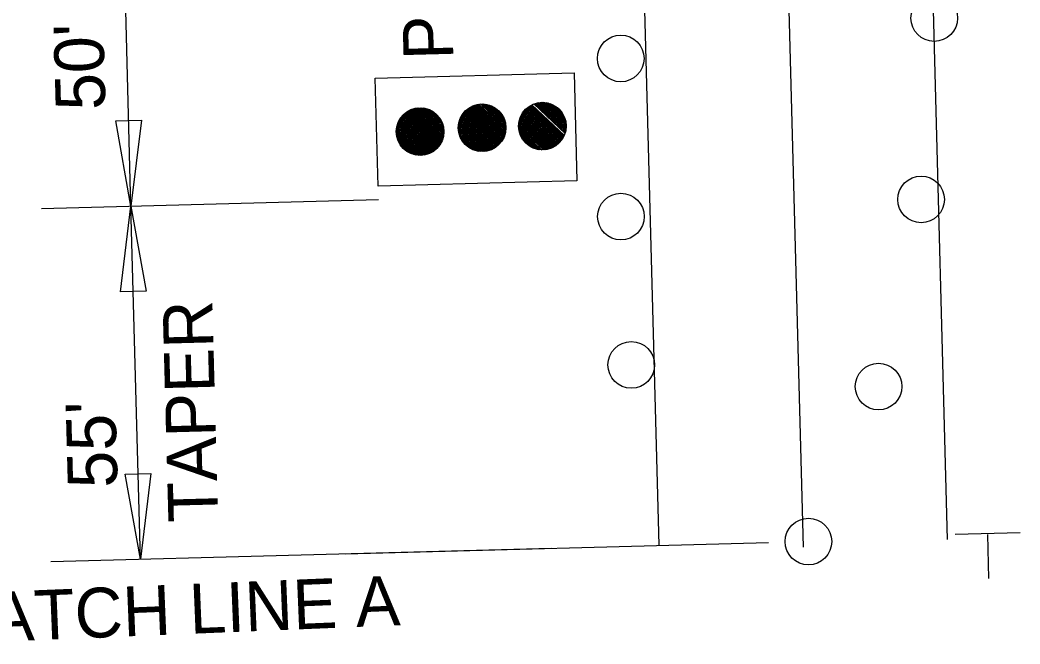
# Model space of a CAD drawing. Extents: x 1929624 to 1932072, y 596315 to 605533.
# Drawn here: x 1931264.8 to 1931385.3, y 596662 to 596737.2 of the extents above; entities that cross this region are included whole.
import ezdxf

# ---------------------------------------------------------------- set-up
doc = ezdxf.new("R2010")
doc.units = 0
doc.layers.add('Default', color=7, linetype='Continuous')

msp = doc.modelspace()

# ---------------------------------------------------------------- linework, layer by layer
at = {"layer": 'Default'}
for p, q in [((1931376.6, 596674.64), (1931372.56, 596825.19)), ((1931359.23, 596673.68), (1931355.29, 596820.56)), ((1931341.84, 596673.92), (1931337.95, 596818.64)), ((1931278.16, 596714.79), (1931277.26, 596748.45)), ((1931315.51, 596722.34), (1931311.46, 596726.18)), ((1931315.57, 596722.45), (1931311.57, 596726.25)), ((1931315.63, 596722.57), (1931311.68, 596726.31)), ((1931315.68, 596722.69), (1931311.8, 596726.37)), ((1931315.73, 596722.82), (1931311.93, 596726.42)), ((1931315.77, 596722.95), (1931312.06, 596726.47)), ((1931315.81, 596723.09), (1931312.19, 596726.52)), ((1931315.84, 596723.23), (1931312.34, 596726.55)), ((1931315.86, 596723.38), (1931312.48, 596726.59)), ((1931315.88, 596723.54), (1931312.64, 596726.61)), ((1931315.89, 596723.71), (1931312.8, 596726.63)), ((1931315.88, 596723.88), (1931312.98, 596726.63)), ((1931315.87, 596724.07), (1931313.16, 596726.63)), ((1931315.84, 596724.26), (1931313.36, 596726.61)), ((1931315.79, 596724.48), (1931313.58, 596726.58)), ((1931315.72, 596724.72), (1931313.83, 596726.52)), ((1931315.6, 596725.01), (1931314.12, 596726.41)), ((1931315.38, 596725.39), (1931314.52, 596726.21)), ((1931322.62, 596722.29), (1931318.44, 596726.25)), ((1931322.7, 596722.39), (1931318.53, 596726.33)), ((1931322.78, 596722.49), (1931318.63, 596726.42)), ((1931322.85, 596722.59), (1931318.73, 596726.5)), ((1931322.92, 596722.69), (1931318.83, 596726.57)), ((1931322.99, 596722.8), (1931318.93, 596726.64)), ((1931323.05, 596722.92), (1931319.04, 596726.71)), ((1931323.1, 596723.04), (1931319.16, 596726.77)), ((1931323.16, 596723.16), (1931319.28, 596726.83)), ((1931323.2, 596723.29), (1931319.4, 596726.89)), ((1931323.25, 596723.42), (1931319.53, 596726.94)), ((1931323.28, 596723.56), (1931319.67, 596726.98)), ((1931323.31, 596723.7), (1931319.81, 596727.02)), ((1931323.34, 596723.85), (1931319.96, 596727.05)), ((1931323.35, 596724.01), (1931320.11, 596727.07)), ((1931323.36, 596724.17), (1931320.28, 596727.09)), ((1931323.36, 596724.34), (1931320.45, 596727.1)), ((1931323.35, 596724.53), (1931320.64, 596727.09)), ((1931323.32, 596724.73), (1931320.84, 596727.08)), ((1931323.27, 596724.95), (1931321.06, 596727.04)), ((1931323.19, 596725.19), (1931321.3, 596726.98)), ((1931323.08, 596725.47), (1931321.6, 596726.88)), ((1931322.85, 596725.86), (1931321.99, 596726.67)), ((1931329.66, 596722.26), (1931325.5, 596726.2)), ((1931329.75, 596722.35), (1931325.58, 596726.3)), ((1931329.84, 596722.44), (1931325.66, 596726.39)), ((1931329.92, 596722.53), (1931325.75, 596726.48)), ((1931330, 596722.63), (1931325.84, 596726.57)), ((1931330.08, 596722.73), (1931325.94, 596726.65)), ((1931330.15, 596722.83), (1931326.04, 596726.73)), ((1931330.22, 596722.94), (1931326.14, 596726.8)), ((1931330.28, 596723.05), (1931326.25, 596726.87)), ((1931330.34, 596723.16), (1931326.36, 596726.93)), ((1931330.4, 596723.28), (1931326.48, 596727)), ((1931330.49, 596723.54), (1931326.73, 596727.1)), ((1931330.53, 596723.67), (1931326.86, 596727.15)), ((1931330.56, 596723.81), (1931327, 596727.19)), ((1931330.59, 596723.96), (1931327.14, 596727.23)), ((1931330.61, 596724.11), (1931327.29, 596727.26)), ((1931330.63, 596724.27), (1931327.45, 596727.28)), ((1931330.63, 596724.44), (1931327.62, 596727.29)), ((1931330.62, 596724.62), (1931327.8, 596727.29)), ((1931330.6, 596724.81), (1931327.99, 596727.28)), ((1931330.57, 596725.02), (1931328.2, 596727.26)), ((1931330.51, 596725.24), (1931328.43, 596727.21)), ((1931330.42, 596725.5), (1931328.69, 596727.14)), ((1931330.26, 596725.82), (1931329.02, 596727)), ((1931329.87, 596726.37), (1931329.59, 596726.63)), ((1931276.34, 596725.05), (1931279.43, 596725.14)), ((1931278.16, 596714.79), (1931276.34, 596725.05)), ((1931279.43, 596725.14), (1931278.16, 596714.79)), ((1931314.45, 596721.27), (1931310.45, 596725.07)), ((1931314.57, 596721.34), (1931310.51, 596725.18)), ((1931314.67, 596721.41), (1931310.58, 596725.29)), ((1931314.77, 596721.49), (1931310.65, 596725.4)), ((1931314.87, 596721.57), (1931310.72, 596725.5)), ((1931314.96, 596721.65), (1931310.8, 596725.6)), ((1931315.05, 596721.74), (1931310.88, 596725.69)), ((1931315.14, 596721.83), (1931310.97, 596725.78)), ((1931315.22, 596721.92), (1931311.06, 596725.87)), ((1931315.3, 596722.02), (1931311.15, 596725.95)), ((1931315.37, 596722.12), (1931311.25, 596726.03)), ((1931315.44, 596722.23), (1931311.35, 596726.11)), ((1931321.44, 596721.51), (1931317.73, 596725.03)), ((1931321.57, 596721.56), (1931317.77, 596725.16)), ((1931321.7, 596721.62), (1931317.82, 596725.29)), ((1931321.81, 596721.67), (1931317.87, 596725.41)), ((1931321.93, 596721.74), (1931317.93, 596725.53)), ((1931322.04, 596721.81), (1931317.99, 596725.65)), ((1931322.15, 596721.88), (1931318.05, 596725.76)), ((1931322.25, 596721.95), (1931318.12, 596725.86)), ((1931322.35, 596722.03), (1931318.2, 596725.96)), ((1931322.44, 596722.11), (1931318.28, 596726.06)), ((1931322.53, 596722.2), (1931318.36, 596726.16)), ((1931328.49, 596721.64), (1931324.94, 596725.01)), ((1931328.63, 596721.68), (1931324.97, 596725.15)), ((1931328.77, 596721.73), (1931325.01, 596725.29)), ((1931328.89, 596721.78), (1931325.06, 596725.42)), ((1931329.02, 596721.84), (1931325.11, 596725.54)), ((1931329.13, 596721.9), (1931325.16, 596725.66)), ((1931329.25, 596721.96), (1931325.22, 596725.78)), ((1931329.36, 596722.03), (1931325.28, 596725.89)), ((1931329.46, 596722.1), (1931325.35, 596726)), ((1931329.56, 596722.18), (1931325.42, 596726.1)), ((1931313.38, 596720.91), (1931310.14, 596723.98)), ((1931313.22, 596720.89), (1931310.14, 596723.82)), ((1931313.54, 596720.93), (1931310.16, 596724.14)), ((1931313.69, 596720.97), (1931310.19, 596724.29)), ((1931313.83, 596721), (1931310.22, 596724.43)), ((1931313.97, 596721.05), (1931310.25, 596724.57)), ((1931314.1, 596721.1), (1931310.29, 596724.7)), ((1931314.22, 596721.15), (1931310.34, 596724.83)), ((1931314.34, 596721.21), (1931310.39, 596724.95)), ((1931320.7, 596721.36), (1931317.61, 596724.28)), ((1931320.52, 596721.35), (1931317.61, 596724.11)), ((1931320.86, 596721.37), (1931317.62, 596724.44)), ((1931320.34, 596721.35), (1931317.63, 596723.92)), ((1931321.02, 596721.4), (1931317.64, 596724.6)), ((1931321.16, 596721.43), (1931317.66, 596724.75)), ((1931321.31, 596721.47), (1931317.69, 596724.89)), ((1931328.04, 596721.56), (1931324.88, 596724.55)), ((1931327.87, 596721.55), (1931324.88, 596724.38)), ((1931328.2, 596721.58), (1931324.89, 596724.71)), ((1931327.69, 596721.54), (1931324.89, 596724.2)), ((1931328.35, 596721.61), (1931324.91, 596724.86)), ((1931327.49, 596721.56), (1931324.91, 596724.01)), ((1931327.28, 596721.58), (1931324.95, 596723.8)), ((1931313.05, 596720.89), (1931310.14, 596723.64)), ((1931312.86, 596720.89), (1931310.15, 596723.46)), ((1931312.66, 596720.91), (1931310.18, 596723.26)), ((1931312.44, 596720.94), (1931310.23, 596723.04)), ((1931312.2, 596721), (1931310.3, 596722.8)), ((1931320.14, 596721.37), (1931317.66, 596723.72)), ((1931319.92, 596721.41), (1931317.7, 596723.5)), ((1931319.67, 596721.47), (1931317.78, 596723.26)), ((1931319.38, 596721.57), (1931317.9, 596722.98)), ((1931318.99, 596721.77), (1931318.12, 596722.59)), ((1931327.05, 596721.63), (1931325.01, 596723.57)), ((1931326.78, 596721.71), (1931325.1, 596723.3)), ((1931326.45, 596721.86), (1931325.27, 596722.98)), ((1931311.91, 596721.11), (1931310.42, 596722.51)), ((1931311.51, 596721.31), (1931310.64, 596722.13)), ((1931267.38, 596714.5), (1931308, 596715.6)), ((1931276.89, 596704.45), (1931278.16, 596714.79)), ((1931279.3, 596672.24), (1931278.16, 596714.79)), ((1931278.16, 596714.79), (1931279.98, 596704.54)), ((1931279.98, 596704.54), (1931276.89, 596704.45)), ((1931277.48, 596682.5), (1931280.57, 596682.58)), ((1931279.3, 596672.24), (1931277.48, 596682.5)), ((1931280.57, 596682.58), (1931279.3, 596672.24)), ((1931377.5, 596675.26), (1931385.32, 596675.47)), ((1931381.39, 596675.24), (1931381.53, 596669.91)), ((1931268.52, 596671.95), (1931328.85, 596673.57)), ((1931304.01, 596672.9), (1931355.02, 596674.27))]:
    msp.add_line(p, q, dxfattribs=at)
msp.add_lwpolyline([(1931307.95, 596717.2), (1931307.61, 596730.18), (1931331.57, 596730.83), (1931331.92, 596717.84)], close=True, dxfattribs=at)
for centre, radius in [((1931374.98, 596737.44), 2.81), ((1931337.2, 596732.57), 2.81), ((1931313.01, 596723.76), 2.87), ((1931320.49, 596724.22), 2.87), ((1931327.75, 596724.42), 2.87), ((1931373.4, 596715.59), 2.81), ((1931337.22, 596713.53), 2.81), ((1931338.47, 596695.66), 2.81), ((1931368.27, 596693.05), 2.81), ((1931359.82, 596674.37), 2.81)]:
    msp.add_circle(centre, radius, dxfattribs=at)

# ---------------------------------------------------------------- texts
for s, rotation, p in [('PORTABLE TRAFFIC SIGNAL SYSTEM', 91.5377, (1931317.03, 596732.48)), ("50'", 91.5377, (1931275.1, 596726.41)), ('TAPER', 91.5377, (1931288.68, 596676.77)), ("  55' ", 91.5377, (1931276.68, 596676.45)), ('MATCH LINE A', 2.3436, (1931254.57, 596662))]:
    msp.add_text(s, height=6, rotation=rotation, dxfattribs=at).set_placement(p)

doc.saveas('drawing.dxf')
